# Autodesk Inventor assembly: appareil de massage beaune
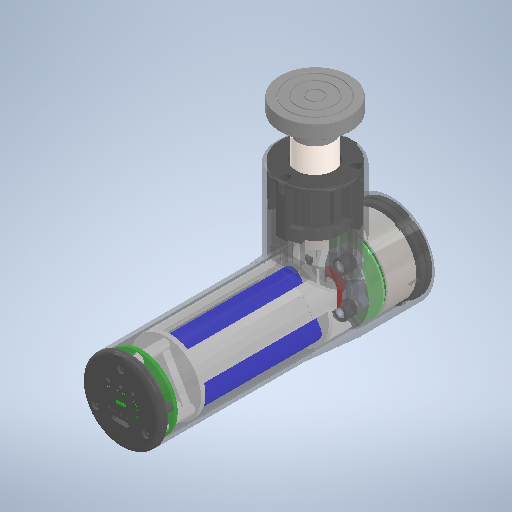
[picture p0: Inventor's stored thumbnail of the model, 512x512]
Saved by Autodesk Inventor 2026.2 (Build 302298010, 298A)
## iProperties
Created: 2026-04
Part Number: appareil de massage beaune
Document SubType Name: Assembly
Designer: mel
Author: mel
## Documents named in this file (5)
- C:\Users\mel\Downloads\18256-itec-20250709t050547z-1-001 (1)\ITEC\Ressources\ITEC00_SW_Appareil_de_massage\S1Appareil_de_massage\S1Appareil_de_massage\appareil de massage beaune.iam
- C:\Users\mel\Downloads\18256-itec-20250709t050547z-1-001 (1)\ITEC\Ressources\ITEC00_SW_Appareil_de_massage\S1Appareil_de_massage\S1Appareil_de_massage\classe moteur.iam
- C:\Users\mel\Downloads\18256-itec-20250709t050547z-1-001 (1)\ITEC\Ressources\ITEC00_SW_Appareil_de_massage\S1Appareil_de_massage\S1Appareil_de_massage\classe palpeur.iam
- C:\Users\mel\Downloads\18256-itec-20250709t050547z-1-001 (1)\ITEC\Ressources\ITEC00_SW_Appareil_de_massage\S1Appareil_de_massage\S1Appareil_de_massage\classe fixe.iam
- C:\Users\mel\Downloads\18256-itec-20250709t050547z-1-001 (1)\ITEC\Ressources\ITEC00_SW_Appareil_de_massage\S1Appareil_de_massage\S1Appareil_de_massage\S1Biellebeaune.ipt
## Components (4 placed, 4 different names)
1. classe moteur:1 [sub-assembly] — Placage:3, Logement:1
2. classe palpeur:1 [sub-assembly] — Placage:1, Placage:4
3. classe fixe:1 [sub-assembly] — Placage:1, Tangente:1, Placage:3
4. S1Biellebeaune:1 — Logement:1, Placage:4
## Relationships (5: Mate 3, Tangent 1, Insert 1)
- Placage:1 [Mate]: classe palpeur:1 ↔ classe fixe:1
- Tangente:1: classe fixe:1
- Placage:3 [Mate]: classe moteur:1 ↔ classe fixe:1
- Logement:1 [Insert]: classe moteur:1 ↔ S1Biellebeaune:1
- Placage:4 [Mate]: classe palpeur:1 ↔ S1Biellebeaune:1
